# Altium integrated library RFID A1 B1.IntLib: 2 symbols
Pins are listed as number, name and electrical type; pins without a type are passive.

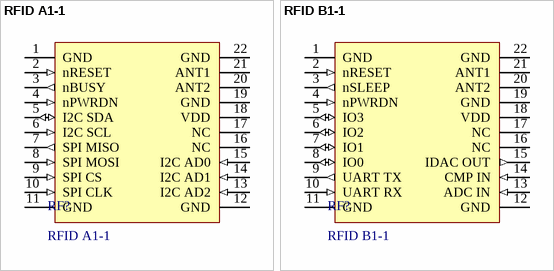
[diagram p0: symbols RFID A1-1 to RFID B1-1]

## RFID A1-1
designator RF?
Manufacturer: Eccel Technology Ltd
footprint RFID_A1_B1_SMT (SMT mounting)
footprint RFID_A1_B1_THT (THT mounting)
pins: 1 GND (power), 2 nRESET (in), 3 nBUSY (out), 4 nPWRDN (in), 5 I2C SDA (io), 6 I2C SCL (in), 7 SPI MISO (out), 8 SPI MOSI (in), 9 SPI CS (in), 10 SPI CLK (in), 11 GND (power), 12 GND (power), 13 I2C AD2 (in), 14 I2C AD1 (in), 15 I2C AD0 (in), 16 NC, 17 NC, 18 VDD (power), 19 GND (power), 20 ANT2, 21 ANT1, 22 GND (power)

## RFID B1-1
designator RF?
Manufacturer: Eccel Technology Ltd
footprint RFID_A1_B1_SMT (SMT mounting)
footprint RFID_A1_B1_THT (THT mounting)
pins: 1 GND (power), 2 nRESET (in), 3 nSLEEP (out), 4 nPWRDN (in), 5 IO3 (io), 6 IO2 (io), 7 IO1 (io), 8 IO0 (io), 9 UART TX (out), 10 UART RX (in), 11 GND (power), 12 GND (power), 13 ADC IN (in), 14 CMP IN (in), 15 IDAC OUT (out), 16 NC, 17 NC, 18 VDD (power), 19 GND (power), 20 ANT2, 21 ANT1, 22 GND (power)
